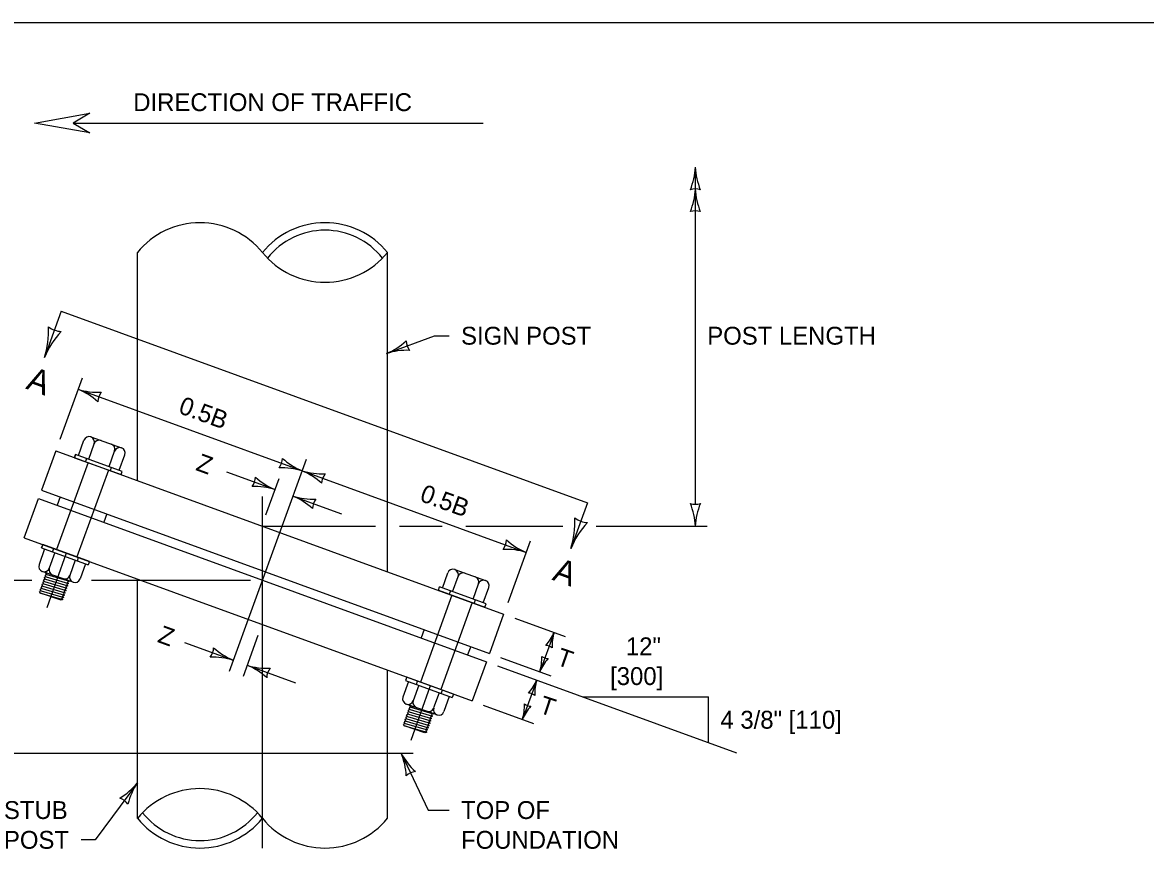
# Model space of a CAD drawing. Extents: x 49991 to 81321, y 49988 to 50028.
# Drawn here: x 50001.718 to 50005.489, y 49996.205 to 49998.999 of the extents above; entities that cross this region are included whole.
import ezdxf

# ---------------------------------------------------------------- set-up
doc = ezdxf.new("R2010")
doc.units = 0
for name, color, linetype in [('Level 1', 7, 'Continuous'), ('Level 2', 7, 'Continuous'), ('Level 3', 7, 'Continuous'), ('Level 4', 7, 'Continuous'), ('Level 5', 7, 'Continuous'), ('Level 6', 7, 'Continuous')]:
    doc.layers.add(name, color=color, linetype=linetype)

msp = doc.modelspace()

# ---------------------------------------------------------------- linework, layer by layer
at = {"layer": 'Level 1'}
for p, q in [((50002.1036, 49997.4609), (50002.1036, 49998.2267)), ((50002.9436, 49997.1548), (50002.9436, 49998.2267)), ((50001.9472, 49997.6075), (50002.0507, 49997.5707)), ((50001.8296, 49997.5607), (50001.7816, 49997.4287)), ((50001.8296, 49997.5607), (50003.3336, 49997.0127)), ((50001.906, 49997.5453), (50001.9242, 49997.5966)), ((50001.9403, 49997.5328), (50001.9587, 49997.5843)), ((50002.0087, 49997.5078), (50002.0272, 49997.5599)), ((50001.8923, 49997.5378), (50001.8962, 49997.5488)), ((50001.896, 49997.5483), (50001.8923, 49997.5378)), ((50001.8923, 49997.5378), (50002.0489, 49997.4808)), ((50002.0528, 49997.4918), (50001.8962, 49997.5488)), ((50001.9329, 49997.5355), (50001.929, 49997.5244)), ((50002.043, 49997.4954), (50002.0616, 49997.5477)), ((50002.0162, 49997.5051), (50002.0122, 49997.4941)), ((50002.0489, 49997.4808), (50002.0528, 49997.4918)), ((50001.7816, 49997.4287), (50003.2856, 49996.8807)), ((50001.7236, 49997.2687), (50001.7716, 49997.4007)), ((50001.7716, 49997.4007), (50003.2756, 49996.8527)), ((50001.8444, 49997.4059), (50001.8342, 49997.3779)), ((50002.001, 49997.3488), (50001.9908, 49997.3208)), ((50001.7236, 49997.2687), (50003.2276, 49996.7207)), ((50001.792, 49997.2313), (50001.7735, 49997.1789)), ((50001.7861, 49997.2459), (50001.7822, 49997.2349)), ((50001.7822, 49997.2349), (50001.7858, 49997.2451)), ((50001.7822, 49997.2349), (50001.9388, 49997.1778)), ((50001.9427, 49997.1888), (50001.7861, 49997.2459)), ((50001.8189, 49997.2215), (50001.8228, 49997.2325)), ((50001.8264, 49997.2188), (50001.808, 49997.1668)), ((50001.8948, 49997.1938), (50001.8766, 49997.1426)), ((50001.9021, 49997.1912), (50001.906, 49997.2022)), ((50001.9427, 49997.1888), (50001.9388, 49997.1778)), ((50001.8881, 49997.1195), (50001.7845, 49997.1559)), ((50001.8002, 49997.145), (50001.7939, 49997.1429)), ((50001.7982, 49997.151), (50001.7967, 49997.1506)), ((50001.8002, 49997.145), (50001.7967, 49997.1506)), ((50001.8002, 49997.145), (50001.8753, 49997.1229)), ((50001.929, 49997.1814), (50001.9111, 49997.1305)), ((50003.1281, 49997.1), (50003.1462, 49997.1512)), ((50003.1692, 49997.1621), (50003.2727, 49997.1253)), ((50001.7893, 49997.1141), (50001.7831, 49997.1119)), ((50001.7866, 49997.1063), (50001.7831, 49997.1119)), ((50001.792, 49997.1218), (50001.7858, 49997.1196)), ((50001.7893, 49997.1141), (50001.7858, 49997.1196)), ((50001.7948, 49997.1295), (50001.7885, 49997.1274)), ((50001.792, 49997.1218), (50001.7885, 49997.1274)), ((50001.7893, 49997.1141), (50001.8645, 49997.092)), ((50001.7975, 49997.1373), (50001.7912, 49997.1351)), ((50001.7948, 49997.1295), (50001.7912, 49997.1351)), ((50001.792, 49997.1218), (50001.8672, 49997.0997)), ((50001.7975, 49997.1373), (50001.7939, 49997.1429)), ((50001.7948, 49997.1295), (50001.8699, 49997.1074)), ((50001.7975, 49997.1373), (50001.8726, 49997.1152)), ((50001.8699, 49997.1074), (50001.8636, 49997.1053)), ((50001.8726, 49997.1152), (50001.8663, 49997.113)), ((50001.8699, 49997.1074), (50001.8663, 49997.113)), ((50001.8753, 49997.1229), (50001.8691, 49997.1208)), ((50001.8726, 49997.1152), (50001.8691, 49997.1208)), ((50001.8753, 49997.1229), (50001.8745, 49997.1243)), ((50002.1038, 49996.3265), (50002.1036, 49997.1302)), ((50003.1624, 49997.0875), (50003.1806, 49997.1389)), ((50003.2308, 49997.0626), (50003.2492, 49997.1146)), ((50001.7812, 49997.0908), (50001.7749, 49997.0887)), ((50001.7784, 49997.0831), (50001.7749, 49997.0887)), ((50001.7839, 49997.0986), (50001.7776, 49997.0964)), ((50001.7812, 49997.0908), (50001.7776, 49997.0964)), ((50001.7784, 49997.0831), (50001.8536, 49997.061)), ((50001.8473, 49997.0589), (50001.7784, 49997.0831)), ((50001.7866, 49997.1063), (50001.7803, 49997.1042)), ((50001.7839, 49997.0986), (50001.7803, 49997.1042)), ((50001.7812, 49997.0908), (50001.8563, 49997.0688)), ((50001.7839, 49997.0986), (50001.859, 49997.0765)), ((50001.7866, 49997.1063), (50001.8617, 49997.0842)), ((50001.859, 49997.0765), (50001.8527, 49997.0744)), ((50001.8563, 49997.0688), (50001.8527, 49997.0744)), ((50001.8617, 49997.0842), (50001.8555, 49997.0821)), ((50001.859, 49997.0765), (50001.8555, 49997.0821)), ((50001.8645, 49997.092), (50001.8582, 49997.0898)), ((50001.8617, 49997.0842), (50001.8582, 49997.0898)), ((50001.8672, 49997.0997), (50001.8609, 49997.0976)), ((50001.8645, 49997.092), (50001.8609, 49997.0976)), ((50001.8672, 49997.0997), (50001.8636, 49997.1053)), ((50003.1144, 49997.0925), (50003.1183, 49997.1036)), ((50003.1144, 49997.0925), (50003.2709, 49997.0355)), ((50003.2748, 49997.0465), (50003.1183, 49997.1036)), ((50003.155, 49997.0902), (50003.1511, 49997.0792)), ((50003.2651, 49997.0501), (50003.2836, 49997.1023)), ((50001.8536, 49997.061), (50001.8473, 49997.0589)), ((50001.8563, 49997.0688), (50001.85, 49997.0666)), ((50001.8536, 49997.061), (50001.85, 49997.0666)), ((50003.2382, 49997.0599), (50003.2342, 49997.0489)), ((50003.2709, 49997.0355), (50003.2748, 49997.0465)), ((50003.3336, 49997.0127), (50003.2856, 49996.8807)), ((50003.0664, 49996.9605), (50003.0562, 49996.9325)), ((50003.223, 49996.9034), (50003.2128, 49996.8754)), ((50003.2756, 49996.8527), (50003.2276, 49996.7207)), ((50002.9435, 49996.3268), (50002.9436, 49996.8242)), ((50003.014, 49996.786), (50002.9955, 49996.7335)), ((50003.0082, 49996.8006), (50003.0043, 49996.7896)), ((50003.0043, 49996.7896), (50003.1608, 49996.7325)), ((50003.1647, 49996.7436), (50003.0082, 49996.8006)), ((50003.0484, 49996.7735), (50003.03, 49996.7214)), ((50003.0409, 49996.7762), (50003.0448, 49996.7873)), ((50003.1168, 49996.7486), (50003.0986, 49996.6972)), ((50003.1242, 49996.7459), (50003.1281, 49996.7569)), ((50003.1511, 49996.7361), (50003.1331, 49996.6851)), ((50003.1647, 49996.7436), (50003.1608, 49996.7325)), ((50003.1101, 49996.6741), (50003.0065, 49996.7105)), ((50003.0195, 49996.6919), (50003.0132, 49996.6897)), ((50003.0222, 49996.6996), (50003.0159, 49996.6975)), ((50003.0195, 49996.6919), (50003.0159, 49996.6975)), ((50003.0222, 49996.6996), (50003.0187, 49996.7052)), ((50003.0187, 49996.7052), (50003.0313, 49996.7015)), ((50003.0195, 49996.6919), (50003.0946, 49996.6698)), ((50003.0222, 49996.6996), (50003.0973, 49996.6775)), ((50003.0086, 49996.6609), (50003.0023, 49996.6588)), ((50003.0059, 49996.6532), (50003.0023, 49996.6588)), ((50003.0113, 49996.6687), (50003.0051, 49996.6665)), ((50003.0086, 49996.6609), (50003.0051, 49996.6665)), ((50003.014, 49996.6764), (50003.0078, 49996.6742)), ((50003.0113, 49996.6687), (50003.0078, 49996.6742)), ((50003.0086, 49996.6609), (50003.0837, 49996.6388)), ((50003.0168, 49996.6841), (50003.0105, 49996.682)), ((50003.014, 49996.6764), (50003.0105, 49996.682)), ((50003.0113, 49996.6687), (50003.0865, 49996.6466)), ((50003.0168, 49996.6841), (50003.0132, 49996.6897)), ((50003.014, 49996.6764), (50003.0892, 49996.6543)), ((50003.0168, 49996.6841), (50003.0919, 49996.662)), ((50003.0892, 49996.6543), (50003.0829, 49996.6522)), ((50003.0919, 49996.662), (50003.0856, 49996.6599)), ((50003.0892, 49996.6543), (50003.0856, 49996.6599)), ((50003.0946, 49996.6698), (50003.0883, 49996.6676)), ((50003.0919, 49996.662), (50003.0883, 49996.6676)), ((50003.0973, 49996.6775), (50003.0911, 49996.6754)), ((50003.0946, 49996.6698), (50003.0911, 49996.6754)), ((50003.0032, 49996.6454), (50002.9969, 49996.6433)), ((50003.0004, 49996.6377), (50002.9969, 49996.6433)), ((50003.0059, 49996.6532), (50002.9996, 49996.651)), ((50003.0032, 49996.6454), (50002.9996, 49996.651)), ((50003.0004, 49996.6377), (50003.0756, 49996.6156)), ((50003.0693, 49996.6135), (50003.0004, 49996.6377)), ((50003.0032, 49996.6454), (50003.0783, 49996.6234)), ((50003.0059, 49996.6532), (50003.081, 49996.6311)), ((50003.0783, 49996.6234), (50003.072, 49996.6212)), ((50003.0756, 49996.6156), (50003.072, 49996.6212)), ((50003.081, 49996.6311), (50003.0747, 49996.629)), ((50003.0783, 49996.6234), (50003.0747, 49996.629)), ((50003.0837, 49996.6388), (50003.0775, 49996.6367)), ((50003.081, 49996.6311), (50003.0775, 49996.6367)), ((50003.0865, 49996.6466), (50003.0802, 49996.6444)), ((50003.0837, 49996.6388), (50003.0802, 49996.6444)), ((50003.0865, 49996.6466), (50003.0829, 49996.6522)), ((50003.0756, 49996.6156), (50003.0693, 49996.6135))]:
    msp.add_line(p, q, dxfattribs=at)
msp.add_lwpolyline([(49999.3835, 49998.9992), (50016.7501, 49998.9992), (50016.7501, 49987.7988), (49999.3835, 49987.7988)], close=True, dxfattribs=at)
for centre, radius, start, end in [((50002.3136, 49998.0559), 0.2707, 39.116, 140.884), ((50002.7336, 49998.0559), 0.2707, 39.116, 140.884), ((50002.7336, 49998.0559), 0.2457, 38.1949, 141.7869), ((50002.7336, 49998.3974), 0.2707, 219.116, 320.884), ((50001.9412, 49997.5905), 0.018, 70.4256, 160.4256), ((50001.9417, 49997.5903), 0.018, 340.4256, 70.4256), ((50001.9756, 49997.5783), 0.018, 70.4256, 160.4256), ((50002.0103, 49997.5659), 0.018, 340.4256, 70.4256), ((50002.0442, 49997.5539), 0.018, 70.4256, 160.4256), ((50002.0447, 49997.5537), 0.018, 340.4256, 70.4256), ((50001.7905, 49997.1728), 0.018, 160.6217, 250.6217), ((50001.791, 49997.1727), 0.018, 250.6217, 340.6217), ((50001.825, 49997.1607), 0.018, 160.6217, 250.6217), ((50003.1632, 49997.1451), 0.018, 70.4256, 160.4256), ((50003.1637, 49997.1449), 0.018, 340.4256, 70.4256), ((50003.1976, 49997.1329), 0.018, 70.4256, 160.4256), ((50001.8597, 49997.1485), 0.018, 250.6217, 340.6217), ((50001.8937, 49997.1366), 0.018, 160.6217, 250.6217), ((50001.8941, 49997.1364), 0.018, 250.6217, 340.6217), ((50003.2323, 49997.1205), 0.018, 340.4256, 70.4256), ((50003.2662, 49997.1085), 0.018, 70.4256, 160.4256), ((50003.2667, 49997.1083), 0.018, 340.4256, 70.4256), ((50003.0125, 49996.7274), 0.018, 160.6217, 250.6217), ((50003.013, 49996.7273), 0.018, 250.6217, 340.6217), ((50003.047, 49996.7153), 0.018, 160.6217, 250.6217), ((50003.0817, 49996.7031), 0.018, 250.6217, 340.6217), ((50003.1157, 49996.6912), 0.018, 160.6217, 250.6217), ((50003.1161, 49996.691), 0.018, 250.6217, 340.6217), ((50002.3138, 49996.1557), 0.2707, 39.1707, 140.8598), ((50002.3138, 49996.4977), 0.2707, 219.1707, 320.8293), ((50002.3138, 49996.4977), 0.2457, 218.2569, 321.7158), ((50002.7335, 49996.4977), 0.2707, 219.1707, 320.8598)]:
    msp.add_arc(centre, radius, start, end, dxfattribs=at)
at = {"layer": 'Level 3'}
for p, q in [((50001.8876, 49998.6615), (50003.265, 49998.6615)), ((50003.9773, 49997.3812), (50003.9773, 49998.5134)), ((50002.9436, 49997.8884), (50003.1016, 49997.9473)), ((50003.1016, 49997.9473), (50003.1507, 49997.9473)), ((50001.9185, 49997.8052), (50001.8433, 49997.5983)), ((50001.9049, 49997.7676), (50002.6545, 49997.4945)), ((50002.4031, 49997.49), (50002.566, 49997.4307)), ((50002.6545, 49997.4945), (50003.4091, 49997.2195)), ((50002.5352, 49997.3461), (50002.5797, 49997.4682)), ((50002.626, 49997.4088), (50002.7889, 49997.3494)), ((50002.5236, 49997.3078), (50002.9036, 49997.3078)), ((50002.9836, 49997.3078), (50003.1268, 49997.3078)), ((50003.2068, 49997.3078), (50003.5326, 49997.3078)), ((50003.6443, 49997.3078), (50004.0173, 49997.3078)), ((50003.4227, 49997.2571), (50003.3474, 49997.0502)), ((50003.4227, 49997.2571), (50003.4082, 49997.2171)), ((50001.3761, 49997.1267), (50001.749, 49997.1267)), ((50001.9493, 49997.1267), (50002.4836, 49997.1267)), ((50003.3713, 49996.9991), (50003.5405, 49996.9375)), ((50002.5084, 49996.9401), (50002.4586, 49996.8032)), ((50003.503, 49996.9511), (50003.455, 49996.8191)), ((50002.2625, 49996.9171), (50002.4255, 49996.8578)), ((50003.3233, 49996.8671), (50003.4926, 49996.8055)), ((50002.4723, 49996.8409), (50002.6352, 49996.7815)), ((50003.3133, 49996.8391), (50004.1156, 49996.5471)), ((50003.4448, 49996.7912), (50003.3969, 49996.6592)), ((50003.6011, 49996.7343), (50004.0216, 49996.7343)), ((50004.0216, 49996.5813), (50004.0216, 49996.7343)), ((50003.2652, 49996.7071), (50003.4344, 49996.6456)), ((50001.3761, 49996.5455), (50003.0293, 49996.5455)), ((50002.9893, 49996.5455), (50003.0798, 49996.3545)), ((50002.1036, 49996.4459), (50001.962, 49996.2545)), ((50003.0798, 49996.3545), (50003.1507, 49996.3545)), ((50001.962, 49996.2545), (50001.915, 49996.2545))]:
    msp.add_line(p, q, dxfattribs=at)
msp.add_lwpolyline([(50001.9445, 49998.6287), (50001.7583, 49998.6615), (50001.9445, 49998.6945), (50001.8877, 49998.6615)], close=True, dxfattribs=at)
for centre, radius, start, end in [((50003.7552, 49998.5226), 0.2223, 337.456, 357.6395), ((50004.21, 49998.5249), 0.233, 182.8273, 202.0772), ((50003.9773, 49998.3852), 0.0548, 72.1388, 107.8612), ((50003.7552, 49998.4491), 0.2223, 337.456, 357.6395), ((50004.21, 49998.4515), 0.233, 182.8273, 202.0772), ((50003.9773, 49998.3118), 0.0548, 72.1388, 107.8612), ((50002.8492, 49998.1018), 0.233, 293.1009, 312.3507), ((50003.0609, 49997.9319), 0.0548, 182.4124, 218.1348), ((50003.009, 49997.676), 0.2223, 87.7296, 107.9131), ((50001.8202, 49997.562), 0.2223, 47.4386, 67.6221), ((50001.9737, 49997.9902), 0.233, 252.8099, 272.0597), ((50002.0253, 49997.7237), 0.0548, 142.1214, 177.8437), ((50002.5364, 49997.5375), 0.0548, 322.1214, 357.8437), ((50002.7415, 49997.6992), 0.2223, 227.4386, 247.6221), ((50002.588, 49997.271), 0.233, 72.8099, 92.0597), ((50002.5722, 49997.288), 0.2223, 47.4339, 67.6174), ((50002.7257, 49997.7162), 0.233, 252.8052, 272.055), ((50002.4456, 49997.4745), 0.0548, 322.1329, 357.8553), ((50002.6506, 49997.6363), 0.2223, 227.4501, 247.6336), ((50002.7773, 49997.4497), 0.0548, 142.1167, 177.839), ((50002.4972, 49997.2081), 0.233, 72.8214, 92.0713), ((50002.5413, 49997.2032), 0.2223, 47.4428, 67.6264), ((50002.6948, 49997.6314), 0.233, 252.8141, 272.064), ((50002.7464, 49997.3649), 0.0548, 142.1257, 177.848), ((50003.9773, 49997.436), 0.0548, 252.1388, 287.8612), ((50003.7446, 49997.2963), 0.233, 2.8273, 22.0772), ((50004.1994, 49997.2986), 0.2223, 157.456, 177.6395), ((50003.2886, 49997.2634), 0.0548, 322.1167, 357.839), ((50003.4937, 49997.4251), 0.2223, 227.4339, 247.6174), ((50003.3402, 49996.9969), 0.233, 72.8052, 92.055), ((50002.305, 49996.9016), 0.0548, 322.1618, 357.8842), ((50002.51, 49997.0635), 0.2223, 227.479, 247.6625), ((50002.3568, 49996.6352), 0.233, 72.8503, 92.1001), ((50003.3066, 49996.8649), 0.1553, 342.8688, 2.1187), ((50003.5921, 49996.7628), 0.1482, 137.4975, 157.681), ((50003.4842, 49996.8995), 0.0365, 232.1803, 267.9027), ((50002.3877, 49996.6353), 0.2223, 47.4537, 67.6372), ((50002.5411, 49997.0635), 0.233, 252.825, 272.0748), ((50002.5927, 49996.797), 0.0548, 142.1365, 177.8588), ((50003.3078, 49996.8475), 0.1482, 317.4729, 337.6564), ((50003.5933, 49996.7454), 0.1553, 162.8442, 182.0941), ((50003.4156, 49996.7109), 0.0365, 52.1557, 87.8781), ((50003.2484, 49996.705), 0.1553, 342.8442, 2.0941), ((50003.5339, 49996.6029), 0.1482, 137.4729, 157.6564), ((50003.4261, 49996.7395), 0.0365, 232.1557, 267.8781), ((50002.7847, 49996.4586), 0.2223, 2.8086, 22.9921), ((50003.1947, 49996.6555), 0.233, 208.1799, 227.4298), ((50003.0442, 49996.4296), 0.0548, 97.4914, 133.2138), ((50001.9305, 49996.5854), 0.2223, 300.9449, 321.1284), ((50002.2975, 49996.3166), 0.233, 146.3162, 165.566), ((50002.0274, 49996.3428), 0.0548, 35.6277, 71.35)]:
    msp.add_arc(centre, radius, start, end, dxfattribs=at)
for centre, major_axis, start_param, end_param in [((50003.3659, 49997.0074), (0.0506, 0.1394), 4.318854, 4.671123), ((50003.6514, 49996.9054), (-0.053, -0.1461), 4.761667, 5.09764), ((50003.4738, 49996.8707), (0.0125, 0.0343), 5.971381, 6.594854)]:
    msp.add_ellipse(centre, major_axis=major_axis, ratio=0.999479, start_param=start_param, end_param=end_param, dxfattribs=at)
at = {"layer": 'Level 4'}
for p, q in [((50001.9381, 49997.5212), (50001.8319, 49997.2293)), ((50002.0064, 49997.4963), (50001.9002, 49997.2044)), ((50003.1601, 49997.0758), (50003.0539, 49996.7839)), ((50003.2284, 49997.0509), (50003.1222, 49996.759))]:
    msp.add_line(p, q, dxfattribs=at)
at = {"layer": 'Level 5'}
for p, q in [((50002.6705, 49997.5312), (50002.4118, 49996.8202)), ((50002.5236, 49996.2267), (50002.5236, 49997.4078)), ((50001.8644, 49997.2175), (50001.7995, 49997.0332)), ((50003.0864, 49996.7721), (50003.0215, 49996.5878))]:
    msp.add_line(p, q, dxfattribs=at)
at = {"layer": 'Level 6'}
for p, q in [((50001.8481, 49998.0295), (50001.7918, 49997.8741)), ((50001.8481, 49998.0295), (50003.6151, 49997.3866)), ((50003.6151, 49997.3866), (50003.5592, 49997.2323))]:
    msp.add_line(p, q, dxfattribs=at)
for centre, radius, start, end in [((50001.4949, 49997.9655), 0.3107, 342.8797, 2.1296), ((50001.8502, 49998.0347), 0.073, 232.1912, 267.9136), ((50002.0661, 49997.7615), 0.2964, 137.5084, 157.6919), ((50003.2623, 49997.3237), 0.3107, 342.88, 2.1298), ((50003.6176, 49997.3929), 0.073, 232.1915, 267.9139), ((50003.8335, 49997.1197), 0.2964, 137.5087, 157.6922)]:
    msp.add_arc(centre, radius, start, end, dxfattribs=at)

# ---------------------------------------------------------------- texts
at = {"layer": 'Level 2'}
for s, p in [('DIRECTION OF TRAFFIC', (50002.0899, 49998.7015)), ('SIGN POST', (50003.1907, 49997.9173)), ('POST LENGTH', (50004.0173, 49997.9173)), ('12"', (50003.7441, 49996.8743)), ('[300]', (50003.6911, 49996.7743)), ('4 3/8" [110]', (50004.0616, 49996.6278)), ('STUB', (50001.6557, 49996.3245)), ('TOP OF', (50003.1907, 49996.3245)), ('POST', (50001.6557, 49996.2245)), ('FOUNDATION', (50003.1907, 49996.2245))]:
    msp.add_text(s, height=0.06, dxfattribs=at).set_placement(p)
for s, height, rotation, p in [('A', 0.08, 340.0071, (50001.7263, 49997.7702)), ('0.5B', 0.06, 339.9825, (50002.2385, 49997.6886)), ('Z', 0.06, 339.9868, (50002.2967, 49997.4968)), ('0.5B', 0.06, 339.9779, (50003.0487, 49997.3934)), ('A', 0.08, 340.0071, (50003.4935, 49997.1284)), ('Z', 0.06, 340.023, (50002.1679, 49996.9196)), ('T', 0.06, 341.0674, (50003.507, 49996.8436)), ('T', 0.06, 341.6994, (50003.4488, 49996.6825))]:
    msp.add_text(s, height=height, rotation=rotation, dxfattribs=at).set_placement(p)

doc.saveas('drawing.dxf')
